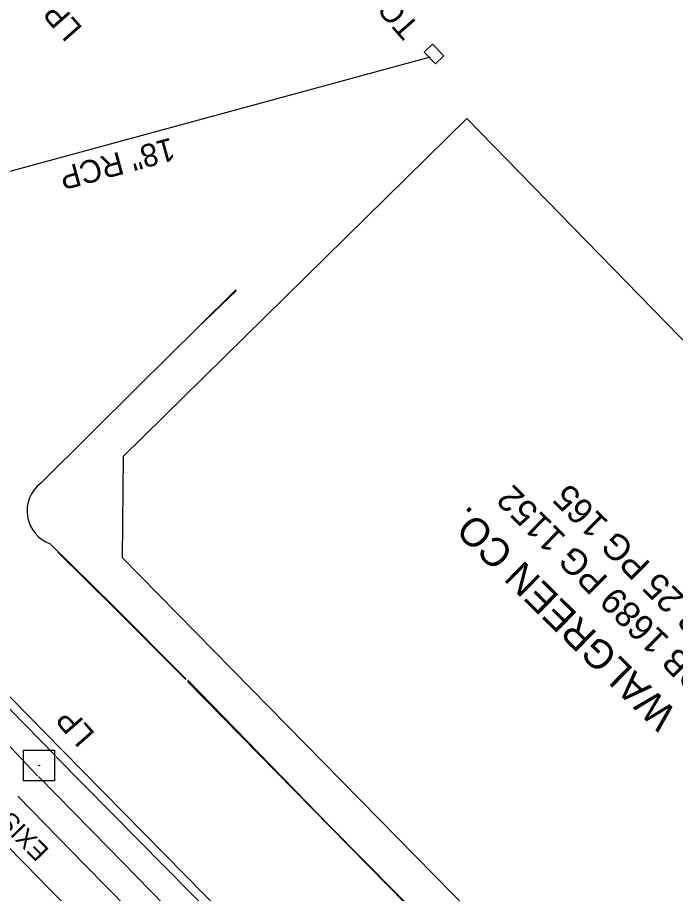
# Model space of a CAD drawing. Extents: x 1263837 to 1268319, y 770628 to 773628.
# Drawn here: x 1267015.5 to 1267130.8, y 772108 to 772261.5 of the extents above; entities that cross this region are included whole.
import ezdxf

# ---------------------------------------------------------------- set-up
doc = ezdxf.new("R2010")
doc.units = 0
for name, color, linetype in [('Exist Building', 7, 'Continuous'), ('Exist Property Deed Book Text', 7, 'Continuous'), ('Exist Roads EOP Other', 7, 'Continuous'), ('Exist Structure Minor Catch Basin', 7, 'Continuous'), ('Exist Structure Minor Catch Basin Top Elevation', 7, 'Continuous'), ('Exist Utilities Other Pole With Base CELL', 7, 'Continuous'), ('Exist Utilities Other Pole With Base Text', 7, 'Continuous'), ('Prop Drainage Structure Tops and Inverts LABEL', 7, 'Continuous'), ('Prop Earthen Structure Base Ditch Special Cut with Rip Rap Detail CELL', 7, 'Continuous'), ('Prop Earthen Structure V Ditch Special Lateral with Rip Rap Detail CELL', 7, 'Continuous'), ('Prop Horizontal Alignment', 7, 'Continuous'), ('Prop Shade Heavy', 7, 'Continuous'), ('Prop SS Fill Line', 7, 'Continuous'), ('Prop SS Fill Text', 7, 'Continuous'), ('Scratch_Level_2', 7, 'Continuous')]:
    doc.layers.add(name, color=color, linetype=linetype)

# ---------------------------------------------------------------- blocks, each defined once
blk = doc.blocks.new('EXIST UTILITIES OTHER POLE WITH BASE')
at = {"layer": 'Exist Utilities Other Pole With Base CELL'}
blk.add_line((0, 0), (0, 0), dxfattribs=at)
blk.add_lwpolyline([(-0.0545, 0.054), (0.0535, 0.054), (0.0535, -0.054), (-0.0545, -0.054), (-0.0545, 0.054)], dxfattribs=at)
blk.add_circle((0, 0), 0.00141, dxfattribs=at)

msp = doc.modelspace()

# ---------------------------------------------------------------- linework, layer by layer
at = {"layer": 'Exist Building'}
msp.add_lwpolyline([(1267094.21, 772243.81), (1267034, 772184.58), (1267033.81, 772166.88), (1267130.22, 772068.76), (1267199.08, 772136.41), (1267094.21, 772243.81)], dxfattribs=at)
at = {"layer": 'Exist Roads EOP Other'}
for points in [[(1267053.84, 772213.68), (1267047.02, 772207.12), (1267036.79, 772197.06), (1267019.53, 772179.94)], [(1267021.21, 772169.28), (1267032.38, 772158.32), (1267045.06, 772145.58)], [(1267018.98, 772128.63), (1267000.34, 772148.37), (1267006.16, 772148.28)], [(1267045.35, 772145.37), (1267070.23, 772119.83), (1267093.74, 772096.02), (1267116.95, 772072.53), (1267125.22, 772063.89), (1267130.09, 772068.65), (1267143.03, 772055.76), (1267145.17, 772055.59), (1267165.74, 772075.85)], [(1267159.91, 771984.79), (1267156.22, 771984.11), (1267135.35, 772004.96), (1267115.66, 772028), (1267106.02, 772039.39), (1267081.61, 772064.71), (1267053.59, 772093.35), (1267031.43, 772116), (1267019.15, 772128.52)], [(1267155.77, 771971.93), (1267154.55, 771978.76), (1267131.51, 772001.83), (1267111.96, 772024.71), (1267102.24, 772036.12), (1267078.14, 772061.16), (1267050.03, 772089.91), (1267027.35, 772112.96), (1267015.53, 772125.08)]]:
    msp.add_lwpolyline(points, dxfattribs=at)
msp.add_ellipse((1267023.3, 772175.07), major_axis=(-2.83, 5.47), ratio=0.999983, start_param=0.182051, end_param=2.319182, dxfattribs=at)
at = {"layer": 'Exist Structure Minor Catch Basin'}
msp.add_lwpolyline([(1267088.21, 772256.84), (1267086.78, 772255.45), (1267088.76, 772253.39), (1267090.2, 772254.79), (1267088.21, 772256.84)], dxfattribs=at)
at = {"layer": 'Prop Horizontal Alignment'}
msp.add_arc((1275094.23, 780056.99), 11329.16, 223.613619, 225.433333, dxfattribs=at)
at = {"layer": 'Prop Shade Heavy'}
msp.add_line((1267087.82, 772254.61), (1266977.53, 772224.56), dxfattribs=at)
at = {"layer": 'Prop SS Fill Line'}
for points in [[(1266955.59, 772199.73), (1266978.16, 772176.79), (1266994.88, 772159.85), (1266999.84, 772154.82), (1267003.28, 772151.35), (1267008.83, 772145.71), (1267022.14, 772132.14)], [(1267022.26, 772131.94), (1267050.92, 772102.94), (1267079.25, 772073.97), (1267108.64, 772044.08), (1267136.87, 772015.29), (1267137.33, 772014.82)]]:
    msp.add_lwpolyline(points, dxfattribs=at)
at = {"layer": 'Prop SS Fill Text'}
msp.add_line((1267053.75, 772213.8), (1267046.99, 772207.17), dxfattribs=at)
for points in [[(1266956.69, 772200.82), (1266979.27, 772177.89), (1266995.97, 772160.91), (1267000.82, 772156.01), (1267004.37, 772152.47), (1267011.63, 772144.97), (1267023.22, 772133.17)], [(1267022.52, 772167.82), (1267032.32, 772158.2), (1267044.97, 772145.48)], [(1267045.25, 772145.18), (1267070.26, 772119.68), (1267093.66, 772095.88), (1267116.76, 772072.32), (1267125.21, 772063.79)], [(1267023.36, 772133.07), (1267051.93, 772104.05), (1267080.48, 772075.07), (1267109.8, 772045.02), (1267138.08, 772016.35), (1267155.56, 771998.02), (1267159.46, 771995.33), (1267161.04, 771992.68)]]:
    msp.add_lwpolyline(points, dxfattribs=at)
at = {"layer": 'Scratch_Level_2'}
msp.add_arc((1275094.23, 780056.99), 11459.16, 216.983333, 225.433333, dxfattribs=at)

# ---------------------------------------------------------------- block references
at = {"layer": 'Exist Utilities Other Pole With Base CELL', "xscale": 50, "yscale": 50}
msp.add_blockref('EXIST UTILITIES OTHER POLE WITH BASE', (1267019.26, 772130.42), dxfattribs=at)

# ---------------------------------------------------------------- texts
at = {"layer": 'Exist Property Deed Book Text'}
for s, p in [('DB 1689 PG 1152', (1267137.07, 772145.62)), ('PB 25 PG 165', (1267139.52, 772153.11))]:
    msp.add_text(s, height=4.5, rotation=135.4239, dxfattribs=at).set_placement(p)
at = {"layer": 'Exist Structure Minor Catch Basin Top Elevation'}
msp.add_text("TOP=1180.23'", height=4, rotation=131.3556, dxfattribs=at).set_placement((1267086.14, 772259.99))
at = {"layer": 'Exist Utilities Other Pole With Base Text'}
for p in [(1267027.01, 772259.66), (1267029.21, 772135.97)]:
    msp.add_text('LP', height=4, rotation=131.3556, dxfattribs=at).set_placement(p)
at = {"layer": 'Prop Drainage Structure Tops and Inverts LABEL'}
msp.add_text('18" RCP', height=4, rotation=195.2407, dxfattribs=at).set_placement((1267042.38, 772240.52))
at = {"layer": 'Prop Earthen Structure Base Ditch Special Cut with Rip Rap Detail CELL'}
msp.add_text('WALGREEN CO.', height=5, rotation=135.4239, dxfattribs=at).set_placement((1267131.28, 772139.71))
at = {"layer": 'Prop Earthen Structure V Ditch Special Lateral with Rip Rap Detail CELL'}
msp.add_text('EXISTING R/W', height=3.2, rotation=134.4261, dxfattribs=at).set_placement((1267021.16, 772115.62))

doc.saveas('drawing.dxf')
